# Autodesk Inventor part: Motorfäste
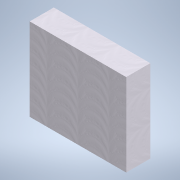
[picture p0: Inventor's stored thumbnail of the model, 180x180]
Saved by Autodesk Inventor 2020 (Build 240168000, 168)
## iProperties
Created: 2019-06
Part Number: Motorfäste
Material: Aluminum 6061, Welded
Document SubType Name: Sheet Metal
Designer: cl
Density: 2.7 g/cm^3
Sheet Metal Rule: Default_mm
Appearance: Weld - Aluminum
Author: cl
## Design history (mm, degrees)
node "Face1"
  sketch "Sketch2"
    geometry: L1 (0, 0)-(145, 0); L2 (145, 0)-(145, -120); L3 (145, -120)-(0, -120); L4 (0, -120)-(0, 0)
    constraints: 8 end point, 2 parallel, 1 horizontal, 1 perpendicular
    dimensions: "d4" = 145 distance of L2.end L3.end; "d5" = 120 distance of L1.end L2.end
node "Flange1"
node "Flange2"
body "Solid2"
face "Plate1" dims "d6" = 4 (= Thickness)
sketch "Sketch3"
  geometry: L1 through (0, 60) direction (0, -1); L2 through (25, 0) direction (1, 0); L3 (50, 0)-(50, 120); L4 (50, 120)-(0, 120)
  constraints: 6 end point, 1 horizontal, 1 perpendicular, 1 vertical
face "Plate2" dims "d6" = 4 (= Thickness), "d7" = 4 (= BendReliefWidth), "d8" = 2 (= BendReliefDepth), "d9" = 8 (= MinimumRemnant), "d10" = 4 (= TransitionRadius), "d11" = 50, "d12" = 90 deg, "d13" = 4 (= BendRadius), "d14" = 16 (= CornerReliefSize), "d15" = 4 (= GapSize), "d16" = 4 (= JacobiRadiusSize), "SeamGap" = 0.01
bend "Bend1" dims "d6" = 4 (= Thickness), "d7" = 4 (= BendReliefWidth), "d8" = 2 (= BendReliefDepth), "d9" = 8 (= MinimumRemnant), "d10" = 4 (= TransitionRadius), "d11" = 50, "d12" = 90 deg, "d13" = 4 (= BendRadius), "SeamGap" = 0.01
feature "Corner1" dims "d11" = 50, "d12" = 90 deg, "d14" = 16 (= CornerReliefSize), "d15" = 4 (= GapSize), "d16" = 4 (= JacobiRadiusSize)
sketch "Sketch4"
  geometry: L1 through (0, 60) direction (0, -1); L2 through (16.5, 0) direction (1, 2.21e-51); L3 (33, 0)-(33, 120); L4 (33, 120)-(0, 120)
  constraints: 6 end point, 1 horizontal, 1 perpendicular, 1 vertical
face "Plate3" dims "d6" = 4 (= Thickness), "d17" = 4 (= BendReliefWidth), "d18" = 2 (= BendReliefDepth), "d19" = 8 (= MinimumRemnant), "d20" = 4 (= TransitionRadius), "d21" = 33, "d22" = 90 deg, "d23" = 4 (= BendRadius), "d24" = 16 (= CornerReliefSize), "d25" = 4 (= GapSize), "d26" = 4 (= JacobiRadiusSize), "SeamGap" = 0.01
bend "Bend2" dims "d6" = 4 (= Thickness), "d17" = 4 (= BendReliefWidth), "d18" = 2 (= BendReliefDepth), "d19" = 8 (= MinimumRemnant), "d20" = 4 (= TransitionRadius), "d21" = 33, "d22" = 90 deg, "d23" = 4 (= BendRadius), "SeamGap" = 0.01
feature "Corner2" dims "d21" = 33, "d22" = 90 deg, "d24" = 16 (= CornerReliefSize), "d25" = 4 (= GapSize), "d26" = 4 (= JacobiRadiusSize)
other parameters: "Thickness" = 4 (derived), "KFactor" = 4.4, "BendRadius" = 4 (= Thickness), "BendReliefWidth" = 4 (= Thickness), "BendReliefDepth" = 2 (= 0.5 x Thickness), "CornerReliefSize" = 16 (= 4 x Thickness), "MinimumRemnant" = 8 (= 2 x Thickness), "TransitionRadius" = 4 (= BendRadius), "JacobiRadiusSize" = 4 (= BendRadius), "GapSize" = 4 (= Thickness)
